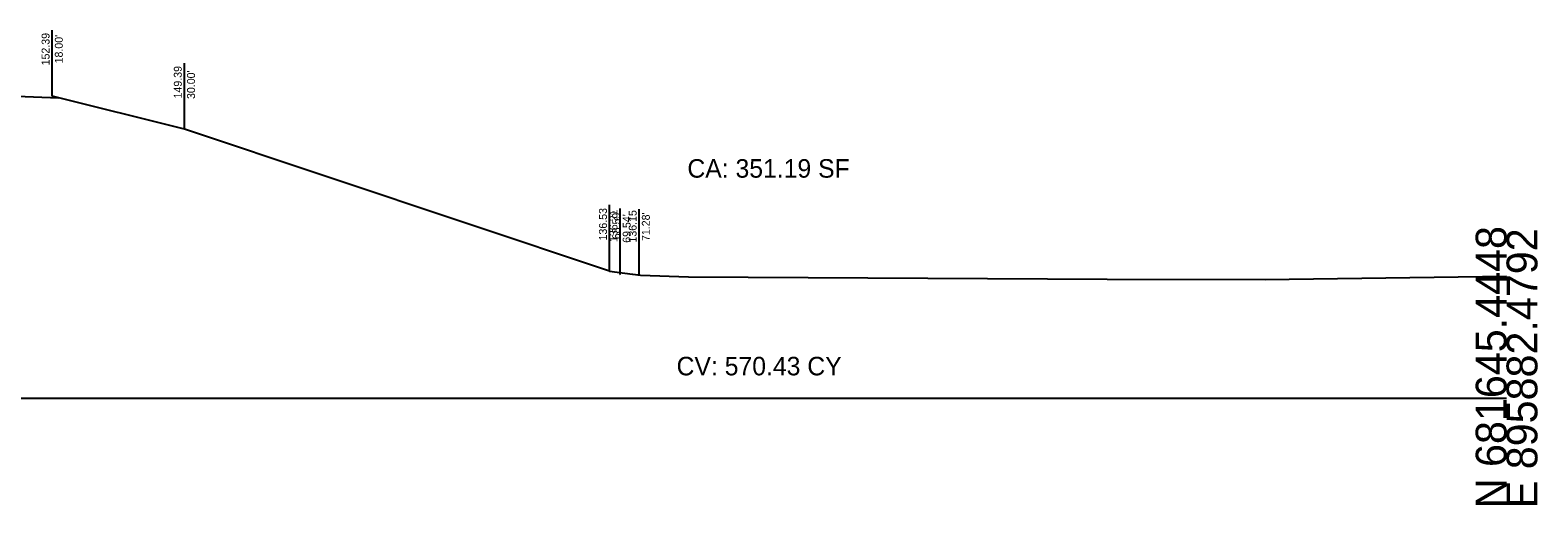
# Model space of a CAD drawing. Extents: x -100 to 4303, y -13 to 10775.
# Drawn here: x 3166 to 3302.8, y 5490.3 to 5533.4 of the extents above; entities that cross this region are included whole.
import ezdxf

# ---------------------------------------------------------------- set-up
doc = ezdxf.new("R2010")
doc.units = 0
for name, color, linetype in [('DTM_CONTOURS_MINOR', 7, 'Continuous'), ('DTM_X_GROUND', 7, 'Continuous'), ('X_PROFILES_1', 7, 'Continuous'), ('XS_CELL', 7, 'Continuous'), ('XS_P_TX_CLEARZONE', 7, 'Continuous'), ('XS_SHEET_EW_TX_AREA', 7, 'Continuous'), ('XS_SHEET_EW_TX_VOLUME', 7, 'Continuous')]:
    doc.layers.add(name, color=color, linetype=linetype)

msp = doc.modelspace()

# ---------------------------------------------------------------- linework, layer by layer
at = {"layer": 'DTM_X_GROUND'}
msp.add_line((3164, 5527.42), (3168.6, 5527.24), dxfattribs=at)
for points in [[(3218.58, 5511.53), (3180, 5524.39), (3180, 5524.39), (3180, 5524.39), (3168, 5527.39)], [(3218.58, 5511.53), (3220.68, 5511.23), (3220.69, 5511.23), (3221.39, 5511.15)], [(3221.39, 5511.15), (3225.75, 5511.01), (3263.76, 5510.78), (3278.1, 5510.76), (3300, 5511.07)]]:
    msp.add_lwpolyline(points, dxfattribs=at)
at = {"layer": 'XS_CELL'}
msp.add_line((3150, 5500), (3300, 5500), dxfattribs=at)
msp.add_line((3150, 5500), (3300, 5500), dxfattribs=at)
at = {"layer": 'XS_P_TX_CLEARZONE'}
for p, q in [((3168, 5527.39), (3168, 5533.39)), ((3168, 5527.39), (3168, 5533.39)), ((3180, 5524.39), (3180, 5530.39)), ((3180, 5524.39), (3180, 5530.39)), ((3180, 5524.39), (3180, 5530.39)), ((3180, 5524.39), (3180, 5530.39)), ((3218.59, 5511.53), (3218.59, 5517.53)), ((3218.59, 5511.53), (3218.59, 5517.53)), ((3219.54, 5511.21), (3219.54, 5517.21)), ((3219.54, 5511.21), (3219.54, 5517.21)), ((3219.54, 5511.21), (3219.54, 5517.21)), ((3219.54, 5511.21), (3219.54, 5517.21)), ((3219.54, 5511.21), (3219.54, 5517.21)), ((3221.28, 5511.15), (3221.28, 5517.15)), ((3221.28, 5511.15), (3221.28, 5517.15)), ((3221.28, 5511.15), (3221.28, 5517.15))]:
    msp.add_line(p, q, dxfattribs=at)

# ---------------------------------------------------------------- texts
at = {"layer": 'DTM_CONTOURS_MINOR'}
msp.add_text('X', height=0.12, dxfattribs=at).set_placement((3219.5, 5511.15))
at = {"layer": 'X_PROFILES_1'}
for p in [(3218.55, 5511.47), (3219.5, 5511.15)]:
    msp.add_text('X', height=0.12, dxfattribs=at).set_placement(p)
at = {"layer": 'XS_CELL'}
for s, p in [('N 681645.4448', (3300, 5490)), ('N 681645.4448', (3300, 5490)), ('E 895882.4792', (3302.8, 5490)), ('E 895882.4792', (3302.8, 5490))]:
    msp.add_text(s, height=2.8, rotation=90, dxfattribs=at).set_placement(p)
at = {"layer": 'XS_P_TX_CLEARZONE'}
for s, p in [('152.39', (3167.76, 5530.19)), ('152.39', (3167.76, 5530.19)), ("18.00'", (3168.96, 5530.37)), ("18.00'", (3168.96, 5530.37)), ('149.39', (3179.76, 5527.19)), ('149.39', (3179.76, 5527.19)), ('149.39', (3179.76, 5527.19)), ('149.39', (3179.76, 5527.19)), ("30.00'", (3180.96, 5527.14)), ("30.00'", (3180.96, 5527.14)), ("30.00'", (3180.96, 5527.14)), ("30.00'", (3180.96, 5527.14)), ('136.53', (3218.35, 5514.3)), ('136.53', (3218.35, 5514.3)), ('136.21', (3219.3, 5514.16)), ('136.21', (3219.3, 5514.16)), ('136.21', (3219.3, 5514.16)), ('136.21', (3219.3, 5514.16)), ('136.21', (3219.3, 5514.16)), ("68.59'", (3219.55, 5514.41)), ("68.59'", (3219.55, 5514.41)), ("69.54'", (3220.5, 5514.09)), ("69.54'", (3220.5, 5514.09)), ("69.54'", (3220.5, 5514.09)), ("69.54'", (3220.5, 5514.09)), ("69.54'", (3220.5, 5514.09)), ('136.15', (3221.04, 5514.11)), ('136.15', (3221.04, 5514.11)), ('136.15', (3221.04, 5514.11)), ("71.28'", (3222.24, 5514.25)), ("71.28'", (3222.24, 5514.25)), ("71.28'", (3222.24, 5514.25))]:
    msp.add_text(s, height=0.72, rotation=90, dxfattribs=at).set_placement(p)
at = {"layer": 'XS_SHEET_EW_TX_AREA'}
msp.add_text('CA: 351.19 SF', height=1.68, dxfattribs=at).set_placement((3225.65, 5520))
at = {"layer": 'XS_SHEET_EW_TX_VOLUME'}
msp.add_text('CV: 570.43 CY', height=1.68, dxfattribs=at).set_placement((3224.67, 5502.06))

doc.saveas('drawing.dxf')
